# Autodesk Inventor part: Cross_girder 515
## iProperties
Shininess: 69.0
Length Units: 11269
Angle Units: 11279
Time Units: 11290
Mass Units: 11283
Length Display Precision: 3
Angle Display Precision: 2
Created: 2001-06
Part Number: Cross_girder 515
Material: Standard
Document SubType Name: Modellieren
Designer: Administrator
Density: 1 g/cm^3
Density: 0.0
Volumn: 0.0
Area: 0.0
PropertySet Name: Model Information
Control State: 0
Master: False
Checked Out: False
Author: Administrator
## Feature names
1. Extrusion1
2. Mirror1
3. Extrusion2
4. Mirror2
